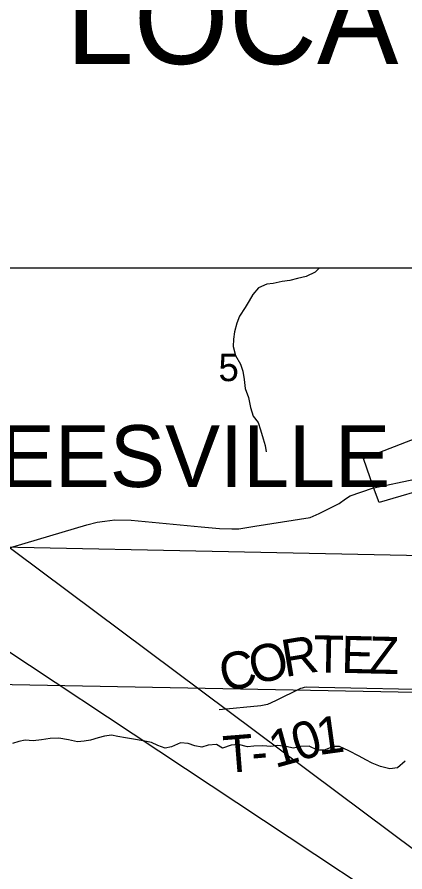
# Model space of a CAD drawing. Extents: x -19.9 to 41.9, y 0 to 32.3.
# Drawn here: x 3.386 to 3.98, y 18.417 to 19.727 of the extents above; entities that cross this region are included whole.
import ezdxf

# ---------------------------------------------------------------- set-up
doc = ezdxf.new("R2010")
doc.units = 0
for name, color, linetype in [('GM_X_Corporation', 7, 'Continuous'), ('GM_X_Corporation_Text', 7, 'Continuous'), ('GM_X_County_Road', 7, 'Continuous'), ('GM_X_Minor_River', 7, 'Continuous'), ('GM_X_Section', 7, 'Continuous'), ('GM_X_Section_Text', 7, 'Continuous'), ('GM_X_Township_Road', 7, 'Continuous'), ('GM_X_Township_Road_Text', 7, 'Continuous'), ('SH_Text', 7, 'Continuous')]:
    doc.layers.add(name, color=color, linetype=linetype)

msp = doc.modelspace()

# ---------------------------------------------------------------- linework, layer by layer
at = {"layer": 'GM_X_Corporation'}
msp.add_lwpolyline([(3.0491, 19.9448), (4.0503, 19.9079), (4.0319, 18.9009), (3.0393, 18.921)], close=True, dxfattribs=at)
msp.add_lwpolyline([(4.0279, 19.0087), (3.9405, 18.9831), (3.9321, 19.0062), (3.9167, 19.0506), (4.0707, 19.1103)], dxfattribs=at)
at = {"layer": 'GM_X_County_Road'}
for points in [[(3.9304, 19.005), (3.9323, 19.0057), (3.9955, 19.0186), (4.0212, 19.029), (4.0489, 19.0402), (4.0535, 19.0412), (4.061, 19.042), (4.0691, 19.0423), (4.0922, 19.0468), (4.1265, 19.0477), (4.2034, 19.0436)], [(3.1193, 18.8382), (3.4928, 18.9488), (3.5085, 18.9528), (3.5203, 18.9546), (3.5357, 18.9565), (3.5607, 18.9559), (3.668, 18.9458), (3.6959, 18.9433), (3.7149, 18.9428), (3.7256, 18.9426), (3.7504, 18.9466), (3.835, 18.9601), (3.8489, 18.9661), (3.8792, 18.9816), (3.889, 18.9886), (3.8962, 18.9933), (3.9304, 19.005)]]:
    msp.add_lwpolyline(points, dxfattribs=at)
at = {"layer": 'GM_X_Minor_River'}
for points in [[(3.8495, 19.3423), (3.8426, 19.336), (3.829, 19.329), (3.8154, 19.3259), (3.8036, 19.3231), (3.7919, 19.3215), (3.7782, 19.3187), (3.7684, 19.3175), (3.7559, 19.3117), (3.7472, 19.3014), (3.7416, 19.2919), (3.7352, 19.2819), (3.7266, 19.2686), (3.7225, 19.2575), (3.7192, 19.2442), (3.7174, 19.2332), (3.7172, 19.2222), (3.7203, 19.2082), (3.728, 19.195), (3.7319, 19.184), (3.7339, 19.1715), (3.7352, 19.1575), (3.7406, 19.1438), (3.7434, 19.1287), (3.7477, 19.1154), (3.7554, 19.1056), (3.7589, 19.0943), (3.7628, 19.0807), (3.7659, 19.0701), (3.7676, 19.0606)], [(3.6689, 18.6081), (3.6582, 18.6103), (3.6479, 18.614), (3.6362, 18.615), (3.6225, 18.6088), (3.6127, 18.6065), (3.6013, 18.6105), (3.5917, 18.6154), (3.5818, 18.6176), (3.5674, 18.6197), (3.5522, 18.6226), (3.5404, 18.6244), (3.5305, 18.6266), (3.5199, 18.625), (3.51, 18.6227), (3.4983, 18.6191), (3.4888, 18.6172), (3.4785, 18.6163), (3.4648, 18.6192), (3.45, 18.6221), (3.4367, 18.6213), (3.4234, 18.6193), (3.4105, 18.618), (3.3984, 18.619), (3.3885, 18.6167), (3.3787, 18.6136)], [(3.9805, 18.5868), (3.9688, 18.5765), (3.9571, 18.5752), (3.9426, 18.5785), (3.93, 18.5837), (3.9205, 18.589), (3.9098, 18.5946), (3.8942, 18.6024), (3.8801, 18.6091), (3.8706, 18.609), (3.8562, 18.6036), (3.8463, 18.6035), (3.8333, 18.6099), (3.8204, 18.6094), (3.809, 18.6066), (3.7984, 18.6092), (3.7851, 18.6106), (3.7748, 18.609), (3.7623, 18.6104), (3.7486, 18.6099), (3.7391, 18.6087), (3.7251, 18.6124), (3.7141, 18.6111), (3.7008, 18.6068), (3.6913, 18.6121), (3.6787, 18.6112), (3.6689, 18.6081)]]:
    msp.add_lwpolyline(points, dxfattribs=at)
at = {"layer": 'GM_X_Section'}
msp.add_lwpolyline([(4.2222, 19.3423), (4.2131, 18.8031), (4.2117, 18.6878), (3.19, 18.7074), (3.2015, 19.3423)], dxfattribs=at)
at = {"layer": 'GM_X_Township_Road'}
msp.add_lwpolyline([(3.6957, 18.6659), (3.7593, 18.6719), (3.7672, 18.6734), (3.7699, 18.674), (3.7824, 18.6796), (3.8205, 18.6985), (3.8232, 18.6993), (3.8265, 18.7), (3.83, 18.7005), (3.8483, 18.7001), (4.044, 18.6962), (4.0604, 18.6965), (4.0708, 18.697), (4.0777, 18.6999), (4.0826, 18.7037), (4.0878, 18.7094), (4.1131, 18.7477), (4.1198, 18.7579), (4.1209, 18.7708), (4.1205, 18.8031)], dxfattribs=at)
at = {"layer": 'SH_Text'}
for points in [[(2.4893, 19.3423), (4.3977, 19.3423), (4.3977, 19.8611), (2.4893, 19.8611)], [(2.8043, 19.3392), (5.2749, 17.495), (2.4893, 19.3392)]]:
    msp.add_lwpolyline(points, close=True, dxfattribs=at)

# ---------------------------------------------------------------- texts
at = {"layer": 'GM_X_Corporation_Text'}
msp.add_text('LEESVILLE', height=0.0947, rotation=0, dxfattribs=at).set_placement((3.2887, 19.0067))
at = {"layer": 'GM_X_Section_Text'}
msp.add_text('5', height=0.0419, rotation=0, dxfattribs=at).set_placement((3.6945, 19.1689))
at = {"layer": 'GM_X_Township_Road_Text'}
for s, rotation, p in [('T', 358.9093, (3.8395, 18.7229)), ('O', 14.4038, (3.7491, 18.7032)), ('R', 9.461, (3.7963, 18.7154)), ('E', 358.6842, (3.882, 18.7221)), ('Z', 358.6842, (3.9245, 18.7211)), ('C', 14.4187, (3.7039, 18.6916)), ('0', 17.8064, (3.8173, 18.5859)), ('1', 7.7912, (3.848, 18.596)), ('1', 15.4492, (3.7811, 18.5759)), ('T', 4.5711, (3.7039, 18.5683)), ('-', 5.222, (3.747, 18.5718))]:
    msp.add_text(s, height=0.0568, rotation=rotation, dxfattribs=at).set_placement(p)
at = {"layer": 'SH_Text'}
msp.add_text('PROJECT LOCATION', height=0.14, dxfattribs=at).set_placement((2.5347, 19.6548))

doc.saveas('drawing.dxf')
